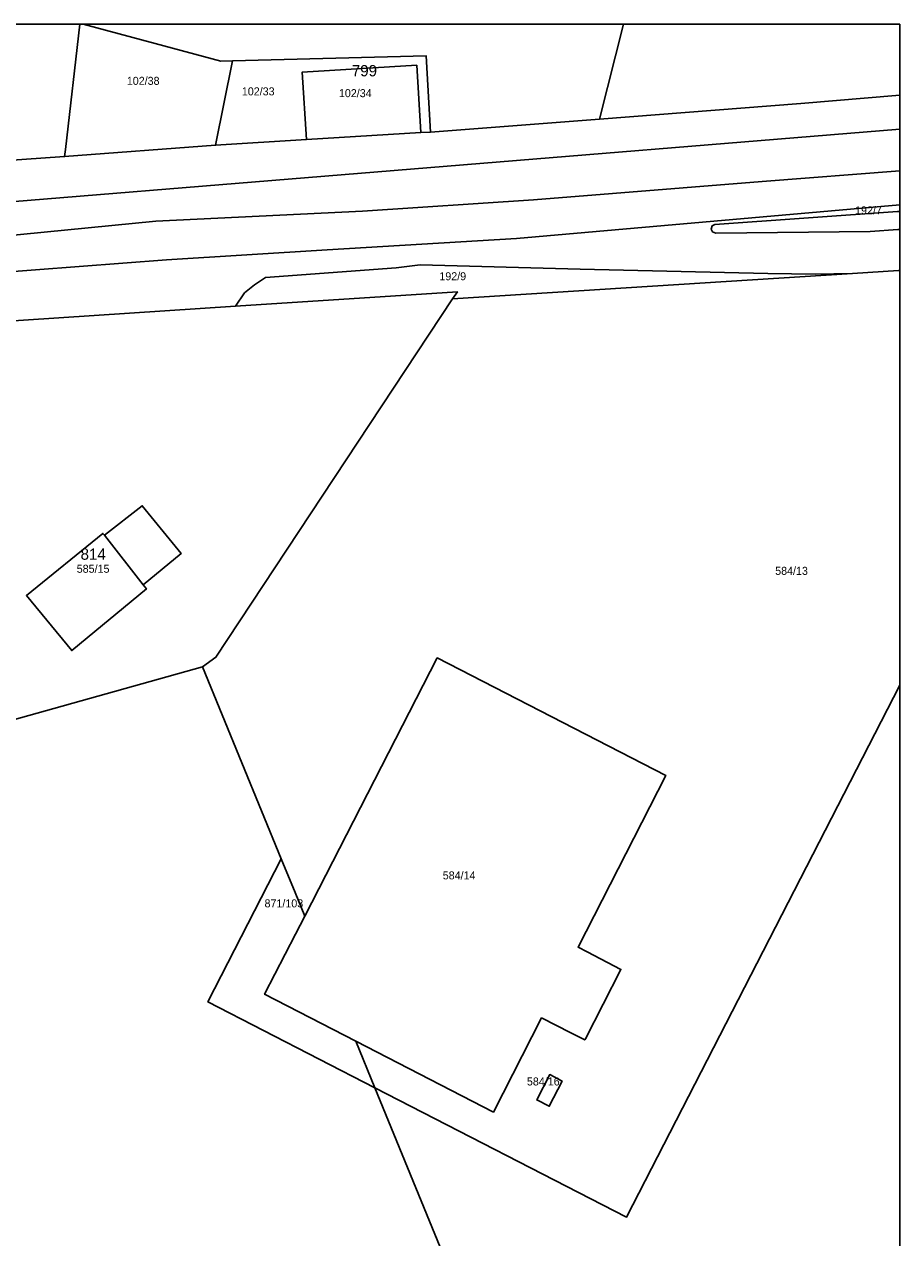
# Model space of a CAD drawing. Extents: x -873642 to -872917, y -1012962 to -1012567.
# Drawn here: x -873009.9 to -872916.9, y -1012696.3 to -1012567.5 of the extents above; entities that cross this region are included whole.
import ezdxf

# ---------------------------------------------------------------- set-up
doc = ezdxf.new("R2010")
doc.units = 0
for name, color, linetype in [('adresni_misto', 7, 'Continuous'), ('cisla_parcelni_kn', 7, 'Continuous'), ('cislo_domovni', 7, 'Continuous'), ('osy_ulic', 7, 'Continuous'), ('parcely_kn', 7, 'Continuous'), ('stavebni_objekty_bydleni', 7, 'Continuous'), ('stavebni_objekty_sluzby', 7, 'Continuous'), ('stavebni_objekty_vyroba', 7, 'Continuous')]:
    doc.layers.add(name, color=color, linetype=linetype)

msp = doc.modelspace()

# ---------------------------------------------------------------- linework, layer by layer
at = {"layer": 'adresni_misto'}
for p, q in [((-872973.53, -1012573.93), (-872973.53, -1012573.93)), ((-873002.34, -1012625.26), (-873002.34, -1012625.26))]:
    msp.add_line(p, q, dxfattribs=at)
at = {"layer": 'osy_ulic'}
msp.add_lwpolyline([(-872916.93, -1012586.66), (-872957.62, -1012590.24), (-872977.73, -1012591.46), (-872994.83, -1012592.51), (-873031.96, -1012595.34), (-873059.56, -1012597.3), (-873096.52, -1012600.28), (-873281.07, -1012614.36), (-873481.95, -1012629.68)], dxfattribs=at)
at = {"layer": 'parcely_kn'}
for p, q in [((-873004.03, -1012567.5), (-873010.8, -1012567.5)), ((-873004.03, -1012567.5), (-873010.8, -1012567.5)), ((-873003.65, -1012567.5), (-873004.03, -1012567.5)), ((-873003.65, -1012567.5), (-873004.03, -1012567.5)), ((-872946.26, -1012567.5), (-873003.65, -1012567.5)), ((-872946.26, -1012567.5), (-873003.65, -1012567.5)), ((-872916.93, -1012578.64), (-872916.93, -1012575.02)), ((-872916.93, -1012578.64), (-872916.93, -1012575.02)), ((-872916.93, -1012583.06), (-872916.93, -1012578.64)), ((-872916.93, -1012583.06), (-872916.93, -1012578.64)), ((-872916.93, -1012587.37), (-872916.93, -1012583.06)), ((-872916.93, -1012589.29), (-872916.93, -1012587.37)), ((-872916.93, -1012589.29), (-872916.93, -1012587.37)), ((-872916.93, -1012593.65), (-872916.93, -1012589.29)), ((-872916.93, -1012637.66), (-872916.93, -1012593.65)), ((-872916.93, -1012637.66), (-872916.93, -1012593.65)), ((-872916.93, -1012790.31), (-872916.93, -1012637.66)), ((-872916.93, -1012790.31), (-872916.93, -1012637.66))]:
    msp.add_line(p, q, dxfattribs=at)
for points in [[(-873018.76, -1012567.5), (-873023.12, -1012582.82), (-873021.3, -1012582.65), (-873005.64, -1012581.55), (-873005.55, -1012580.78), (-873004.03, -1012567.5)], [(-873018.76, -1012567.5), (-873023.12, -1012582.82), (-873021.3, -1012582.65), (-873005.64, -1012581.55), (-873005.55, -1012580.78), (-873004.03, -1012567.5)], [(-873004.03, -1012567.5), (-873005.55, -1012580.78), (-873005.64, -1012581.55), (-872989.6, -1012580.34), (-872987.79, -1012571.38), (-872989.03, -1012571.4), (-872996.01, -1012569.53), (-873003.65, -1012567.5)], [(-873004.03, -1012567.5), (-873005.55, -1012580.78), (-873005.64, -1012581.55), (-872989.6, -1012580.34), (-872987.79, -1012571.38), (-872989.03, -1012571.4), (-872996.01, -1012569.53), (-873003.65, -1012567.5)], [(-873003.65, -1012567.5), (-872996.01, -1012569.53), (-872989.03, -1012571.4), (-872987.79, -1012571.38), (-872967.23, -1012570.86), (-872966.78, -1012578.95), (-872948.82, -1012577.56), (-872946.26, -1012567.5)], [(-873003.65, -1012567.5), (-872996.01, -1012569.53), (-872989.03, -1012571.4), (-872987.79, -1012571.38), (-872967.23, -1012570.86), (-872966.78, -1012578.95), (-872948.82, -1012577.56), (-872946.26, -1012567.5)], [(-872946.26, -1012567.5), (-872948.82, -1012577.56), (-872927.42, -1012575.9), (-872916.93, -1012575.02)], [(-872946.26, -1012567.5), (-872948.82, -1012577.56), (-872927.42, -1012575.9), (-872916.93, -1012575.02)], [(-872916.93, -1012575.02), (-872916.93, -1012567.5), (-872946.26, -1012567.5)], [(-872916.93, -1012575.02), (-872916.93, -1012567.5), (-872946.26, -1012567.5)], [(-872916.93, -1012575.02), (-872927.42, -1012575.9), (-872948.82, -1012577.56), (-872966.78, -1012578.95), (-872967.8, -1012579), (-872979.96, -1012579.73), (-872989.6, -1012580.34), (-873005.64, -1012581.55), (-873021.3, -1012582.65), (-873023.12, -1012582.82), (-873024.38, -1012587.43), (-872916.93, -1012578.64)], [(-872916.93, -1012575.02), (-872927.42, -1012575.9), (-872948.82, -1012577.56), (-872966.78, -1012578.95), (-872967.8, -1012579), (-872979.96, -1012579.73), (-872989.6, -1012580.34), (-873005.64, -1012581.55), (-873021.3, -1012582.65), (-873023.12, -1012582.82), (-873024.38, -1012587.43), (-872916.93, -1012578.64)], [(-872916.93, -1012578.64), (-873024.38, -1012587.43), (-873054.1, -1012589.49), (-873050.36, -1012591.35), (-873047.29, -1012592.28), (-873043.04, -1012592.4), (-873022.23, -1012590.98), (-872995.95, -1012588.42), (-872974.01, -1012587.35), (-872955.82, -1012586.14), (-872931.53, -1012584.18), (-872916.93, -1012583.06)], [(-872916.93, -1012578.64), (-873024.38, -1012587.43), (-873054.1, -1012589.49), (-873050.36, -1012591.35), (-873047.29, -1012592.28), (-873043.04, -1012592.4), (-873022.23, -1012590.98), (-872995.95, -1012588.42), (-872974.01, -1012587.35), (-872955.82, -1012586.14), (-872931.53, -1012584.18), (-872916.93, -1012583.06)], [(-872916.93, -1012583.06), (-872931.53, -1012584.18), (-872955.82, -1012586.14), (-872974.01, -1012587.35), (-872995.95, -1012588.42), (-873022.23, -1012590.98), (-873043.04, -1012592.4), (-873047.29, -1012592.28), (-873050.36, -1012591.35), (-873054.1, -1012589.49), (-873075.21, -1012592.8), (-873143.44, -1012597.91), (-873216.55, -1012603.73)], [(-872916.93, -1012587.37), (-872917.17, -1012587.39), (-872936.56, -1012588.76), (-872936.85, -1012588.89), (-872936.96, -1012589.25), (-872936.83, -1012589.54), (-872936.45, -1012589.67), (-872920.06, -1012589.51), (-872917.12, -1012589.3), (-872916.93, -1012589.29)], [(-872916.93, -1012587.37), (-872917.17, -1012587.39), (-872936.56, -1012588.76), (-872936.85, -1012588.89), (-872936.96, -1012589.25), (-872936.83, -1012589.54), (-872936.45, -1012589.67), (-872920.06, -1012589.51), (-872917.12, -1012589.3), (-872916.93, -1012589.29)], [(-872916.93, -1012589.29), (-872917.12, -1012589.3), (-872920.06, -1012589.51), (-872936.45, -1012589.67), (-872936.83, -1012589.54), (-872936.96, -1012589.25), (-872936.85, -1012588.89), (-872936.56, -1012588.76), (-872917.17, -1012587.39), (-872916.93, -1012587.37)], [(-873273.72, -1012619.94), (-873079.43, -1012607.12), (-873054.9, -1012604.66), (-873052.37, -1012604.41), (-873050.31, -1012602.24), (-873047.57, -1012601.38), (-872987.5, -1012597.44), (-872986.52, -1012596.03), (-872985.48, -1012595.15), (-872984.31, -1012594.39), (-872970.43, -1012593.36), (-872967.88, -1012593.04), (-872950.87, -1012593.5), (-872930.93, -1012593.98), (-872925.9, -1012594.03), (-872921.95, -1012593.97), (-872917.07, -1012593.66), (-872916.93, -1012593.65)], [(-872916.93, -1012593.65), (-872917.07, -1012593.66), (-872921.95, -1012593.97), (-872964.43, -1012596.64), (-872989.57, -1012634.71), (-872990.98, -1012635.74), (-872982.62, -1012656.13), (-872981.16, -1012659.69), (-872980.13, -1012662.2), (-872966.06, -1012634.79), (-872941.76, -1012647.27), (-872951.1, -1012665.5), (-872950.13, -1012666), (-872946.55, -1012667.86), (-872950.31, -1012675.23), (-872950.38, -1012675.35), (-872951.86, -1012674.59), (-872954.98, -1012673), (-872960.09, -1012683), (-872974.69, -1012675.49), (-872972.67, -1012680.42), (-872945.94, -1012694.15), (-872916.93, -1012637.66)], [(-872916.93, -1012593.65), (-872917.07, -1012593.66), (-872921.95, -1012593.97), (-872964.43, -1012596.64), (-872989.57, -1012634.71), (-872990.98, -1012635.74), (-872982.62, -1012656.13), (-872981.16, -1012659.69), (-872980.13, -1012662.2), (-872966.06, -1012634.79), (-872941.76, -1012647.27), (-872951.1, -1012665.5), (-872950.13, -1012666), (-872946.55, -1012667.86), (-872950.31, -1012675.23), (-872950.38, -1012675.35), (-872951.86, -1012674.59), (-872954.98, -1012673), (-872960.09, -1012683), (-872974.69, -1012675.49), (-872972.67, -1012680.42), (-872945.94, -1012694.15), (-872916.93, -1012637.66)], [(-873026.14, -1012645.58), (-872990.98, -1012635.74), (-872982.62, -1012656.13), (-872990.41, -1012671.31), (-872972.67, -1012680.42), (-872927.45, -1012790.77)], [(-873026.14, -1012645.58), (-872990.98, -1012635.74), (-872982.62, -1012656.13), (-872990.41, -1012671.31), (-872972.67, -1012680.42), (-872927.45, -1012790.77)], [(-872916.93, -1012637.66), (-872945.94, -1012694.15), (-872972.67, -1012680.42), (-872927.45, -1012790.77), (-872916.93, -1012790.31)], [(-872916.93, -1012637.66), (-872945.94, -1012694.15), (-872972.67, -1012680.42), (-872927.45, -1012790.77), (-872916.93, -1012790.31)], [(-872952.79, -1012679.72), (-872954.16, -1012682.39), (-872955.49, -1012681.71), (-872954.1, -1012679.02), (-872952.79, -1012679.72)], [(-872952.79, -1012679.72), (-872954.16, -1012682.39), (-872955.49, -1012681.71), (-872954.1, -1012679.02), (-872952.79, -1012679.72)]]:
    msp.add_lwpolyline(points, dxfattribs=at)
for points in [[(-872989.6, -1012580.34), (-872987.79, -1012571.38), (-872967.23, -1012570.86), (-872966.78, -1012578.95), (-872967.8, -1012579), (-872968.23, -1012571.85), (-872980.39, -1012572.58), (-872979.96, -1012579.73)], [(-872989.6, -1012580.34), (-872987.79, -1012571.38), (-872967.23, -1012570.86), (-872966.78, -1012578.95), (-872967.8, -1012579), (-872968.23, -1012571.85), (-872980.39, -1012572.58), (-872979.96, -1012579.73)], [(-872980.39, -1012572.58), (-872968.23, -1012571.85), (-872967.8, -1012579), (-872979.96, -1012579.73)], [(-872980.39, -1012572.58), (-872968.23, -1012571.85), (-872967.8, -1012579), (-872979.96, -1012579.73)], [(-872987.5, -1012597.44), (-872986.52, -1012596.03), (-872985.48, -1012595.15), (-872984.31, -1012594.39), (-872970.43, -1012593.36), (-872967.88, -1012593.04), (-872950.87, -1012593.5), (-872930.93, -1012593.98), (-872925.9, -1012594.03), (-872921.95, -1012593.97), (-872964.43, -1012596.64), (-872963.92, -1012595.9)], [(-872987.5, -1012597.44), (-872986.52, -1012596.03), (-872985.48, -1012595.15), (-872984.31, -1012594.39), (-872970.43, -1012593.36), (-872967.88, -1012593.04), (-872950.87, -1012593.5), (-872930.93, -1012593.98), (-872925.9, -1012594.03), (-872921.95, -1012593.97), (-872964.43, -1012596.64), (-872963.92, -1012595.9)], [(-873047.57, -1012601.38), (-872987.5, -1012597.44), (-872963.92, -1012595.9), (-872964.43, -1012596.64), (-872989.57, -1012634.71), (-872990.98, -1012635.74), (-873026.14, -1012645.58), (-873065.38, -1012647.07), (-873065.7, -1012641.7), (-873062.75, -1012637.7), (-873058.34, -1012622.19), (-873059.76, -1012619.22), (-873054.28, -1012608.24), (-873052.37, -1012604.41), (-873050.31, -1012602.24)], [(-873047.57, -1012601.38), (-872987.5, -1012597.44), (-872963.92, -1012595.9), (-872964.43, -1012596.64), (-872989.57, -1012634.71), (-872990.98, -1012635.74), (-873026.14, -1012645.58), (-873065.38, -1012647.07), (-873065.7, -1012641.7), (-873062.75, -1012637.7), (-873058.34, -1012622.19), (-873059.76, -1012619.22), (-873054.28, -1012608.24), (-873052.37, -1012604.41), (-873050.31, -1012602.24)], [(-872996.94, -1012627.45), (-873004.88, -1012634.01), (-873009.7, -1012628.16), (-873001.56, -1012621.56), (-873001.4, -1012621.75), (-872997.39, -1012618.63), (-872993.25, -1012623.69), (-872997.31, -1012627.01)], [(-873009.7, -1012628.16), (-873004.88, -1012634.01), (-872996.94, -1012627.45), (-872997.31, -1012627.01), (-872993.25, -1012623.69), (-872997.39, -1012618.63), (-873001.4, -1012621.75), (-873001.56, -1012621.56)], [(-872996.94, -1012627.45), (-873004.88, -1012634.01), (-873009.7, -1012628.16), (-873001.56, -1012621.56), (-873001.4, -1012621.75), (-872997.39, -1012618.63), (-872993.25, -1012623.69), (-872997.31, -1012627.01)], [(-873009.7, -1012628.16), (-873004.88, -1012634.01), (-872996.94, -1012627.45), (-872997.31, -1012627.01), (-872993.25, -1012623.69), (-872997.39, -1012618.63), (-873001.4, -1012621.75), (-873001.56, -1012621.56)], [(-872966.06, -1012634.79), (-872941.76, -1012647.27), (-872951.1, -1012665.5), (-872950.13, -1012666), (-872946.55, -1012667.86), (-872950.31, -1012675.23), (-872950.38, -1012675.35), (-872951.86, -1012674.59), (-872954.98, -1012673), (-872960.09, -1012683), (-872974.69, -1012675.49), (-872984.4, -1012670.5), (-872981.12, -1012664.12), (-872980.13, -1012662.2)], [(-872966.06, -1012634.79), (-872941.76, -1012647.27), (-872951.1, -1012665.5), (-872950.13, -1012666), (-872946.55, -1012667.86), (-872950.31, -1012675.23), (-872950.38, -1012675.35), (-872951.86, -1012674.59), (-872954.98, -1012673), (-872960.09, -1012683), (-872974.69, -1012675.49), (-872984.4, -1012670.5), (-872981.12, -1012664.12), (-872980.13, -1012662.2)], [(-872990.41, -1012671.31), (-872982.62, -1012656.13), (-872981.16, -1012659.69), (-872980.13, -1012662.2), (-872981.12, -1012664.12), (-872984.4, -1012670.5), (-872974.69, -1012675.49), (-872972.67, -1012680.42)], [(-872990.41, -1012671.31), (-872982.62, -1012656.13), (-872981.16, -1012659.69), (-872980.13, -1012662.2), (-872981.12, -1012664.12), (-872984.4, -1012670.5), (-872974.69, -1012675.49), (-872972.67, -1012680.42)], [(-872954.1, -1012679.02), (-872952.79, -1012679.72), (-872954.16, -1012682.39), (-872955.49, -1012681.71)], [(-872954.1, -1012679.02), (-872952.79, -1012679.72), (-872954.16, -1012682.39), (-872955.49, -1012681.71)]]:
    msp.add_lwpolyline(points, close=True, dxfattribs=at)
at = {"layer": 'stavebni_objekty_bydleni'}
for points in [[(-872979.96, -1012579.73), (-872980.39, -1012572.58), (-872968.23, -1012571.85), (-872967.8, -1012579)], [(-873009.7, -1012628.16), (-873001.56, -1012621.56), (-873001.4, -1012621.75), (-872997.31, -1012627.01), (-872996.94, -1012627.45), (-873004.88, -1012634.01)]]:
    msp.add_lwpolyline(points, close=True, dxfattribs=at)
at = {"layer": 'stavebni_objekty_sluzby'}
msp.add_lwpolyline([(-872966.06, -1012634.79), (-872941.76, -1012647.27), (-872951.1, -1012665.5), (-872950.13, -1012666), (-872946.55, -1012667.86), (-872950.31, -1012675.23), (-872950.38, -1012675.35), (-872951.86, -1012674.59), (-872954.98, -1012673), (-872960.09, -1012683), (-872974.69, -1012675.49), (-872984.4, -1012670.5), (-872981.12, -1012664.12), (-872980.13, -1012662.2)], close=True, dxfattribs=at)
at = {"layer": 'stavebni_objekty_vyroba'}
msp.add_lwpolyline([(-872954.1, -1012679.02), (-872952.79, -1012679.72), (-872954.16, -1012682.39), (-872955.49, -1012681.71)], close=True, dxfattribs=at)

# ---------------------------------------------------------------- texts
at = {"layer": 'cisla_parcelni_kn'}
for s, p in [('102/38', (-872999.03, -1012573.93)), ('102/38', (-872999.03, -1012573.93)), ('102/33', (-872986.81, -1012575.05)), ('102/33', (-872986.81, -1012575.05)), ('102/34', (-872976.5, -1012575.24)), ('102/34', (-872976.5, -1012575.24)), ('192/7', (-872921.67, -1012587.68)), ('192/7', (-872921.67, -1012587.68)), ('192/9', (-872965.83, -1012594.68)), ('192/9', (-872965.83, -1012594.68)), ('585/15', (-873004.35, -1012625.74)), ('585/15', (-873004.35, -1012625.74)), ('584/13', (-872930.16, -1012625.96)), ('584/13', (-872930.16, -1012625.96)), ('584/14', (-872965.47, -1012658.3)), ('584/14', (-872965.47, -1012658.3)), ('871/103', (-872984.4, -1012661.27)), ('871/103', (-872984.4, -1012661.27)), ('584/16', (-872956.53, -1012680.18)), ('584/16', (-872956.53, -1012680.18))]:
    msp.add_text(s, height=0.85, dxfattribs=at).set_placement(p)
at = {"layer": 'cislo_domovni'}
for s, p in [('799', (-872975.13, -1012573.03)), ('814', (-873003.94, -1012624.36))]:
    msp.add_text(s, height=1.2, dxfattribs=at).set_placement(p)

doc.saveas('drawing.dxf')
